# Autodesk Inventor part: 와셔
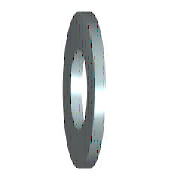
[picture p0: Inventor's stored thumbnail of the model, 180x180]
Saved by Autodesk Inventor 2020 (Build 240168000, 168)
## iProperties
IsCustomPart: 0
Created: 2012-02
Part Number: 와셔
Material: 강철, 연강
Description: 평면 와셔 - 일반 시리즈 - 제품 등급 C
Document SubType Name: Modeling
Standard: ISO 7091
Designer: mduedu
Standard Revision: Second edition 2000-06-01
Standards Organization: ISO
Language: ko-KR
Size Designation: ST 4 - 100 HV
Categories: <MemberInstance><Categories><Category DisplayName="조임쇠" InternalName="e4da775c-781d-43d5-af7c-5136215cf5a6" Mnemonic="FSTN"><Category DisplayName="와셔" InternalN
Density: 7.86 g/cm^3
Mass: 0.492315 g
Surface Area: 1.70824 cm^2
Volume: 0.0626355 cm^3
Appearance: 파란색 - 벽 페인트 - 광택
Author: mduedu
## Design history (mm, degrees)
sketch "스케치"
  geometry: C1 r 5 at (0, 0); C2 r 2.25 at (0, 0); 1 further point
  constraints: 2 centre point, 2 coincident
  dimensions: "d0" = 4.5 diameter of C2 (= SD1); "d1" = 10 diameter of C1 (= SD2)
extrude "본체" new body sketch "스케치" distance "d2" = 1 (= SD); taper "d3" = 0 deg
workaxis "Work Axis1"
workplane "Work Plane1"
body "Solid1"
other parameters: "SD1" = 4.5 [user parameter; used in 1 equation term], "SD2" = 10 [user parameter; used in 1 equation term], "SD" = 1 [user parameter; used in 1 equation term], "d4" = 0, "d5" = 0, "d6" = 0, "d7" = 0, "NND" = 4 [user parameter]
